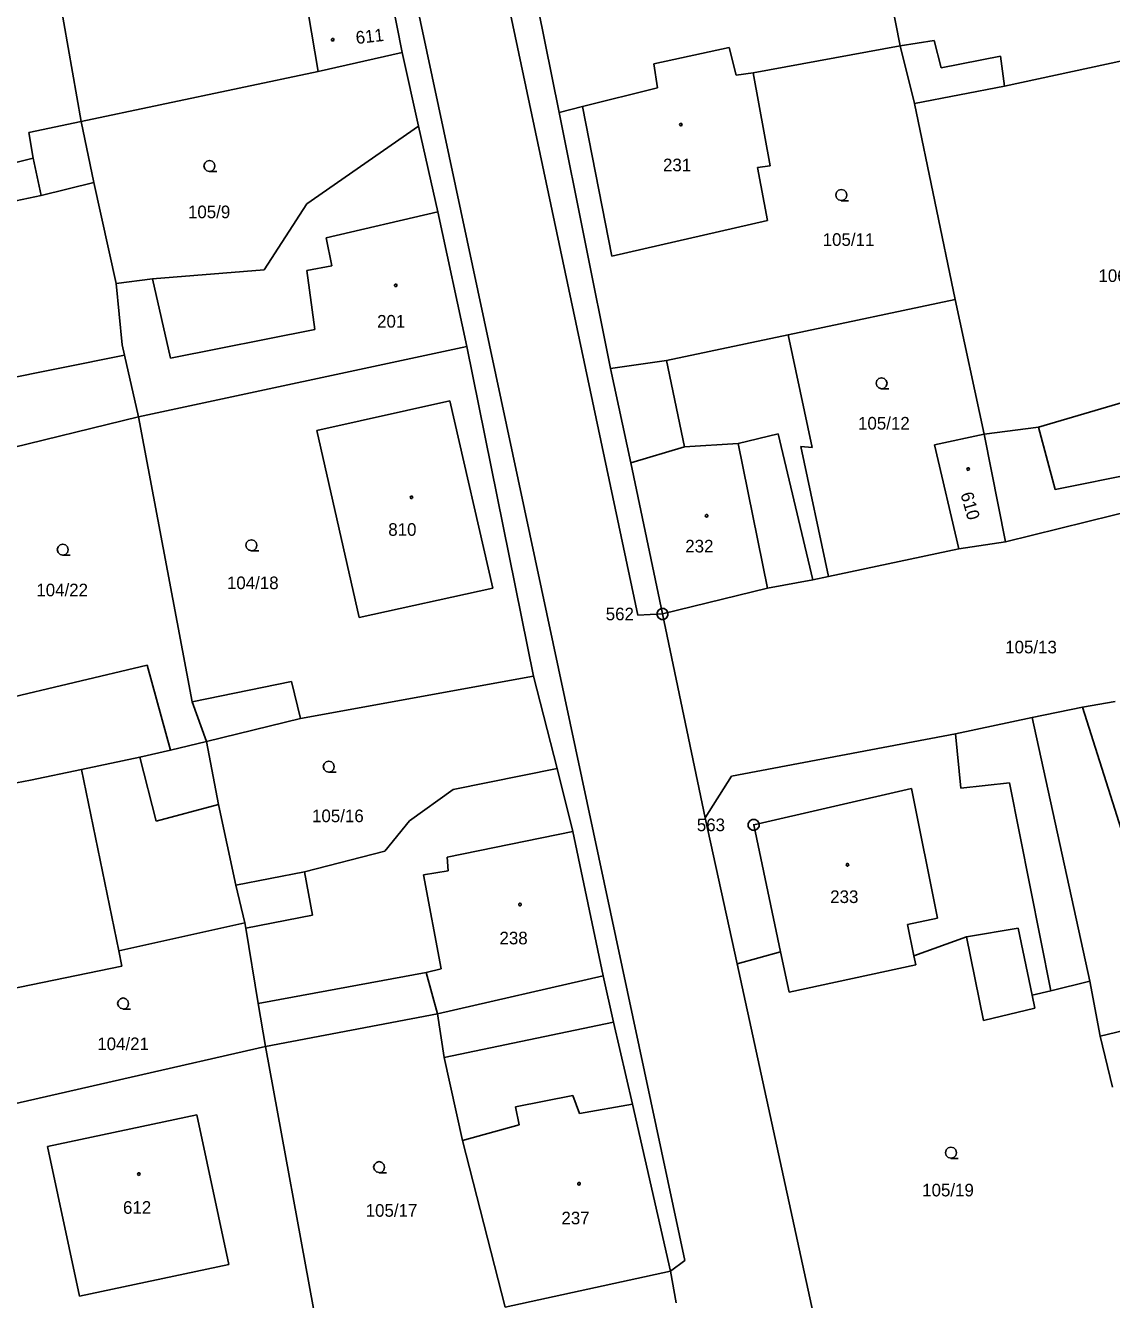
# Model space of a CAD drawing. Extents: x -757994 to -755874, y -1047691 to -1046119.
# Drawn here: x -756709.6 to -756636.5, y -1047105.4 to -1047019.6 of the extents above; entities that cross this region are included whole.
import ezdxf

# ---------------------------------------------------------------- set-up
doc = ezdxf.new("R2010")
doc.units = 0
doc.layers.add('katastrální mapa', color=7, linetype='Continuous')

msp = doc.modelspace()

# ---------------------------------------------------------------- linework, layer by layer
at = {"layer": 'katastrální mapa'}
for p, q in [((-756701.95, -1046901.14), (-756668.39, -1047059.3)), ((-756707.71, -1046903.74), (-756665.23, -1047102.74)), ((-756652.26, -1047013.32), (-756650.75, -1047021)), ((-756705.85, -1047026.09), (-756707.32, -1047017.76)), ((-756685, -1047017.62), (-756684.26, -1047021.44)), ((-756675.13, -1047018.38), (-756673.7, -1047025.49)), ((-756689.9, -1047022.72), (-756690.59, -1047018.75)), ((-756626.1, -1047019.92), (-756643.72, -1047023.72)), ((-756667.31, -1047022.22), (-756662.24, -1047021.12)), ((-756662.24, -1047021.12), (-756661.77, -1047022.98)), ((-756650.75, -1047021), (-756660.64, -1047022.81)), ((-756650.75, -1047021), (-756648.45, -1047020.63)), ((-756650.75, -1047021), (-756649.78, -1047024.89)), ((-756648.45, -1047020.63), (-756647.98, -1047022.47)), ((-756689.9, -1047022.72), (-756684.26, -1047021.44)), ((-756684.26, -1047021.44), (-756683.15, -1047026.41)), ((-756647.98, -1047022.47), (-756644, -1047021.7)), ((-756644, -1047021.7), (-756643.72, -1047023.72)), ((-756705.85, -1047026.09), (-756689.9, -1047022.72)), ((-756667.08, -1047023.83), (-756667.31, -1047022.22)), ((-756661.77, -1047022.98), (-756660.64, -1047022.81)), ((-756660.64, -1047022.81), (-756659.49, -1047029.08)), ((-756643.72, -1047023.72), (-756649.78, -1047024.89)), ((-756672.11, -1047025.09), (-756667.08, -1047023.83)), ((-756672.11, -1047025.09), (-756673.7, -1047025.49)), ((-756673.7, -1047025.49), (-756670.24, -1047042.72)), ((-756670.15, -1047035.16), (-756672.11, -1047025.09)), ((-756649.78, -1047024.89), (-756647.05, -1047038.07)), ((-756709.39, -1047026.83), (-756705.85, -1047026.09)), ((-756705, -1047030.19), (-756705.85, -1047026.09)), ((-756709.08, -1047028.56), (-756709.39, -1047026.83)), ((-756690.67, -1047031.63), (-756683.15, -1047026.41)), ((-756683.15, -1047026.41), (-756681.86, -1047032.17)), ((-756716.05, -1047030.25), (-756709.08, -1047028.56)), ((-756709.08, -1047028.56), (-756708.55, -1047031.06)), ((-756659.49, -1047029.08), (-756660.34, -1047029.18)), ((-756660.34, -1047029.18), (-756659.68, -1047032.76)), ((-756708.55, -1047031.06), (-756705, -1047030.19)), ((-756703.5, -1047037), (-756705, -1047030.19)), ((-756715.51, -1047032.52), (-756708.55, -1047031.06)), ((-756693.55, -1047036.07), (-756690.67, -1047031.63)), ((-756689.37, -1047033.91), (-756681.86, -1047032.17)), ((-756681.86, -1047032.17), (-756679.91, -1047041.22)), ((-756659.68, -1047032.76), (-756670.15, -1047035.16)), ((-756688.98, -1047035.8), (-756689.37, -1047033.91)), ((-756690.67, -1047036.11), (-756688.98, -1047035.8)), ((-756703.5, -1047037), (-756701.05, -1047036.67)), ((-756701.05, -1047036.67), (-756693.55, -1047036.07)), ((-756701.05, -1047036.67), (-756699.84, -1047042.02)), ((-756690.14, -1047040.09), (-756690.67, -1047036.11)), ((-756703.1, -1047041.13), (-756703.5, -1047037)), ((-756647.05, -1047038.07), (-756658.28, -1047040.45)), ((-756645.1, -1047047.13), (-756647.05, -1047038.07)), ((-756699.84, -1047042.02), (-756690.14, -1047040.09)), ((-756658.28, -1047040.45), (-756666.46, -1047042.18)), ((-756656.67, -1047048.03), (-756658.28, -1047040.45)), ((-756714.13, -1047044.07), (-756702.94, -1047041.82)), ((-756703.1, -1047041.13), (-756702.94, -1047041.82)), ((-756702.94, -1047041.82), (-756701.99, -1047045.97)), ((-756701.99, -1047045.97), (-756679.91, -1047041.22)), ((-756679.91, -1047041.22), (-756675.41, -1047063.42)), ((-756666.46, -1047042.18), (-756670.24, -1047042.72)), ((-756665.26, -1047047.98), (-756666.46, -1047042.18)), ((-756670.24, -1047042.72), (-756668.87, -1047049.07)), ((-756630.95, -1047043.56), (-756641.44, -1047046.67)), ((-756689.99, -1047046.88), (-756681.04, -1047044.88)), ((-756681.04, -1047044.88), (-756678.15, -1047057.5)), ((-756714.12, -1047048.91), (-756701.99, -1047045.97)), ((-756701.99, -1047045.97), (-756698.39, -1047065.15)), ((-756687.14, -1047059.47), (-756689.99, -1047046.88)), ((-756641.44, -1047046.67), (-756645.1, -1047047.13)), ((-756640.32, -1047050.86), (-756641.44, -1047046.67)), ((-756661.65, -1047047.76), (-756665.26, -1047047.98)), ((-756658.95, -1047047.11), (-756661.65, -1047047.76)), ((-756661.65, -1047047.76), (-756659.68, -1047057.5)), ((-756656.62, -1047056.93), (-756658.95, -1047047.11)), ((-756648.44, -1047047.84), (-756645.1, -1047047.13)), ((-756643.66, -1047054.37), (-756645.1, -1047047.13)), ((-756665.26, -1047047.98), (-756668.87, -1047049.07)), ((-756655.57, -1047056.71), (-756657.43, -1047047.95)), ((-756657.43, -1047047.95), (-756656.67, -1047048.03)), ((-756646.79, -1047054.84), (-756648.44, -1047047.84)), ((-756668.87, -1047049.07), (-756666.73, -1047059.23)), ((-756634.72, -1047049.74), (-756640.32, -1047050.86)), ((-756634.27, -1047052.06), (-756643.66, -1047054.37)), ((-756643.66, -1047054.37), (-756646.79, -1047054.84)), ((-756646.79, -1047054.84), (-756655.57, -1047056.71)), ((-756656.62, -1047056.93), (-756659.68, -1047057.5)), ((-756655.57, -1047056.71), (-756656.62, -1047056.93)), ((-756678.15, -1047057.5), (-756687.14, -1047059.47)), ((-756659.68, -1047057.5), (-756666.73, -1047059.23)), ((-756668.39, -1047059.3), (-756666.73, -1047059.23)), ((-756666.755, -1047059.23), (-756666.705, -1047059.23)), ((-756666.73, -1047059.23), (-756663.86, -1047072.95)), ((-756711.24, -1047065), (-756701.41, -1047062.67)), ((-756701.41, -1047062.67), (-756699.84, -1047068.39)), ((-756698.39, -1047065.15), (-756691.71, -1047063.77)), ((-756691.71, -1047063.77), (-756691.1, -1047066.27)), ((-756691.1, -1047066.27), (-756675.41, -1047063.42)), ((-756675.41, -1047063.42), (-756673.83, -1047069.63)), ((-756698.39, -1047065.15), (-756697.42, -1047067.82)), ((-756638.47, -1047065.5), (-756641.86, -1047066.19)), ((-756636.27, -1047065.11), (-756638.47, -1047065.5)), ((-756638.47, -1047065.5), (-756635.57, -1047074.64)), ((-756697.42, -1047067.82), (-756691.1, -1047066.27)), ((-756641.86, -1047066.19), (-756647.01, -1047067.29)), ((-756641.86, -1047066.19), (-756637.98, -1047083.94)), ((-756647.01, -1047067.29), (-756662.1, -1047070.15)), ((-756646.67, -1047070.94), (-756647.01, -1047067.29)), ((-756701.9, -1047068.86), (-756699.84, -1047068.39)), ((-756699.84, -1047068.39), (-756697.42, -1047067.82)), ((-756696.62, -1047072.05), (-756697.42, -1047067.82)), ((-756705.83, -1047069.69), (-756701.9, -1047068.86)), ((-756700.81, -1047073.17), (-756701.9, -1047068.86)), ((-756709.26, -1047070.42), (-756705.83, -1047069.69)), ((-756703.33, -1047081.9), (-756705.83, -1047069.69)), ((-756680.82, -1047071.04), (-756673.83, -1047069.63)), ((-756673.83, -1047069.63), (-756672.76, -1047073.87)), ((-756710.2, -1047070.6), (-756709.26, -1047070.42)), ((-756662.1, -1047070.15), (-756663.86, -1047072.95)), ((-756643.38, -1047070.59), (-756646.67, -1047070.94)), ((-756640.6, -1047084.58), (-756643.38, -1047070.59)), ((-756683.76, -1047073.16), (-756680.82, -1047071.04)), ((-756660.6, -1047073.42), (-756649.98, -1047070.98)), ((-756649.98, -1047070.98), (-756648.22, -1047079.7)), ((-756696.62, -1047072.05), (-756700.81, -1047073.17)), ((-756695.45, -1047077.48), (-756696.62, -1047072.05)), ((-756685.42, -1047075.2), (-756683.76, -1047073.16)), ((-756663.86, -1047072.95), (-756661.72, -1047082.77)), ((-756660.625, -1047073.42), (-756660.575, -1047073.42)), ((-756658.79, -1047081.96), (-756660.6, -1047073.42)), ((-756681.22, -1047075.59), (-756672.76, -1047073.87)), ((-756672.76, -1047073.87), (-756670.74, -1047083.58)), ((-756690.82, -1047076.57), (-756685.42, -1047075.2)), ((-756681.17, -1047076.51), (-756681.22, -1047075.59)), ((-756695.45, -1047077.48), (-756690.82, -1047076.57)), ((-756690.3, -1047079.49), (-756690.82, -1047076.57)), ((-756682.82, -1047076.79), (-756681.17, -1047076.51)), ((-756681.63, -1047083.1), (-756682.82, -1047076.79)), ((-756694.85, -1047080.01), (-756695.45, -1047077.48)), ((-756694.77, -1047080.37), (-756690.3, -1047079.49)), ((-756703.33, -1047081.9), (-756694.85, -1047080.01)), ((-756694.85, -1047080.01), (-756694.77, -1047080.37)), ((-756694.77, -1047080.37), (-756693.94, -1047085.44)), ((-756648.22, -1047079.7), (-756650.26, -1047080.13)), ((-756650.26, -1047080.13), (-756649.82, -1047082.24)), ((-756646.29, -1047080.96), (-756642.81, -1047080.37)), ((-756642.81, -1047080.37), (-756641.85, -1047084.89)), ((-756649.82, -1047082.24), (-756646.29, -1047080.96)), ((-756646.29, -1047080.96), (-756645.14, -1047086.58)), ((-756703.12, -1047082.93), (-756703.33, -1047081.9)), ((-756661.72, -1047082.77), (-756658.79, -1047081.96)), ((-756658.79, -1047081.96), (-756658.21, -1047084.68)), ((-756715.51, -1047085.47), (-756703.12, -1047082.93)), ((-756661.72, -1047082.77), (-756655.08, -1047113.24)), ((-756658.21, -1047084.68), (-756649.69, -1047082.85)), ((-756649.82, -1047082.24), (-756649.69, -1047082.85)), ((-756693.94, -1047085.44), (-756682.64, -1047083.35)), ((-756682.64, -1047083.35), (-756681.63, -1047083.1)), ((-756682.64, -1047083.35), (-756681.87, -1047086.13)), ((-756681.87, -1047086.13), (-756670.74, -1047083.58)), ((-756670.74, -1047083.58), (-756670.03, -1047086.69)), ((-756640.6, -1047084.58), (-756641.85, -1047084.89)), ((-756637.98, -1047083.94), (-756640.6, -1047084.58)), ((-756637.98, -1047083.94), (-756637.28, -1047087.64)), ((-756693.94, -1047085.44), (-756693.46, -1047088.33)), ((-756641.85, -1047084.89), (-756641.67, -1047085.76)), ((-756693.46, -1047088.33), (-756681.87, -1047086.13)), ((-756681.43, -1047089.07), (-756681.87, -1047086.13)), ((-756641.67, -1047085.76), (-756645.14, -1047086.58)), ((-756670.03, -1047086.69), (-756681.43, -1047089.07)), ((-756670.03, -1047086.69), (-756668.76, -1047092.21)), ((-756637.28, -1047087.64), (-756633.93, -1047086.84)), ((-756637.28, -1047087.64), (-756636.46, -1047091.06)), ((-756713.97, -1047093.01), (-756693.46, -1047088.33)), ((-756689.77, -1047108.45), (-756693.46, -1047088.33)), ((-756680.19, -1047094.66), (-756681.43, -1047089.07)), ((-756676.64, -1047092.4), (-756672.78, -1047091.63)), ((-756676.39, -1047093.61), (-756676.64, -1047092.4)), ((-756672.78, -1047091.63), (-756672.33, -1047092.84)), ((-756672.33, -1047092.84), (-756668.76, -1047092.21)), ((-756668.76, -1047092.21), (-756666.19, -1047103.45)), ((-756708.12, -1047095.07), (-756698.07, -1047092.93)), ((-756698.07, -1047092.93), (-756695.92, -1047103)), ((-756680.19, -1047094.66), (-756676.39, -1047093.61)), ((-756677.33, -1047105.87), (-756680.19, -1047094.66)), ((-756705.98, -1047105.14), (-756708.12, -1047095.07)), ((-756695.92, -1047103), (-756705.98, -1047105.14)), ((-756677.33, -1047105.87), (-756666.19, -1047103.45)), ((-756665.23, -1047102.74), (-756666.19, -1047103.45)), ((-756666.19, -1047103.45), (-756665.81, -1047105.58))]:
    msp.add_line(p, q, dxfattribs=at)
for points in [[(-756688.93, -1047020.505), (-756688.88, -1047020.515), (-756688.855, -1047020.56), (-756688.845, -1047020.59), (-756688.855, -1047020.635), (-756688.895, -1047020.67), (-756688.93, -1047020.675), (-756688.975, -1047020.66), (-756689.005, -1047020.63), (-756689.015, -1047020.59), (-756689.005, -1047020.545), (-756688.965, -1047020.51)], [(-756665.5, -1047026.215), (-756665.45, -1047026.225), (-756665.425, -1047026.27), (-756665.415, -1047026.3), (-756665.425, -1047026.345), (-756665.465, -1047026.38), (-756665.5, -1047026.385), (-756665.545, -1047026.37), (-756665.575, -1047026.34), (-756665.585, -1047026.3), (-756665.575, -1047026.255), (-756665.535, -1047026.22)], [(-756684.69, -1047037.035), (-756684.64, -1047037.045), (-756684.615, -1047037.09), (-756684.605, -1047037.12), (-756684.615, -1047037.165), (-756684.655, -1047037.2), (-756684.69, -1047037.205), (-756684.735, -1047037.19), (-756684.765, -1047037.16), (-756684.775, -1047037.12), (-756684.765, -1047037.075), (-756684.725, -1047037.04)], [(-756646.17, -1047049.395), (-756646.12, -1047049.405), (-756646.095, -1047049.45), (-756646.085, -1047049.48), (-756646.095, -1047049.525), (-756646.135, -1047049.56), (-756646.17, -1047049.565), (-756646.215, -1047049.55), (-756646.245, -1047049.52), (-756646.255, -1047049.48), (-756646.245, -1047049.435), (-756646.205, -1047049.4)], [(-756683.63, -1047051.295), (-756683.58, -1047051.305), (-756683.555, -1047051.35), (-756683.545, -1047051.38), (-756683.555, -1047051.425), (-756683.595, -1047051.46), (-756683.63, -1047051.465), (-756683.675, -1047051.45), (-756683.705, -1047051.42), (-756683.715, -1047051.38), (-756683.705, -1047051.335), (-756683.665, -1047051.3)], [(-756663.77, -1047052.535), (-756663.72, -1047052.545), (-756663.695, -1047052.59), (-756663.685, -1047052.62), (-756663.695, -1047052.665), (-756663.735, -1047052.7), (-756663.77, -1047052.705), (-756663.815, -1047052.69), (-756663.845, -1047052.66), (-756663.855, -1047052.62), (-756663.845, -1047052.575), (-756663.805, -1047052.54)], [(-756666.635, -1047058.87), (-756666.465, -1047058.965), (-756666.37, -1047059.135), (-756666.37, -1047059.33), (-756666.465, -1047059.5), (-756666.635, -1047059.595), (-756666.83, -1047059.595), (-756667, -1047059.5), (-756667.095, -1047059.33), (-756667.095, -1047059.135), (-756667, -1047058.965), (-756666.83, -1047058.87)], [(-756660.505, -1047073.06), (-756660.335, -1047073.155), (-756660.24, -1047073.325), (-756660.24, -1047073.52), (-756660.335, -1047073.69), (-756660.505, -1047073.785), (-756660.7, -1047073.785), (-756660.87, -1047073.69), (-756660.965, -1047073.52), (-756660.965, -1047073.325), (-756660.87, -1047073.155), (-756660.7, -1047073.06)], [(-756654.29, -1047076.025), (-756654.24, -1047076.035), (-756654.215, -1047076.08), (-756654.205, -1047076.11), (-756654.215, -1047076.155), (-756654.255, -1047076.19), (-756654.29, -1047076.195), (-756654.335, -1047076.18), (-756654.365, -1047076.15), (-756654.375, -1047076.11), (-756654.365, -1047076.065), (-756654.325, -1047076.03)], [(-756676.33, -1047078.695), (-756676.28, -1047078.705), (-756676.255, -1047078.75), (-756676.245, -1047078.78), (-756676.255, -1047078.825), (-756676.295, -1047078.86), (-756676.33, -1047078.865), (-756676.375, -1047078.85), (-756676.405, -1047078.82), (-756676.415, -1047078.78), (-756676.405, -1047078.735), (-756676.365, -1047078.7)], [(-756701.98, -1047096.835), (-756701.93, -1047096.845), (-756701.905, -1047096.89), (-756701.895, -1047096.92), (-756701.905, -1047096.965), (-756701.945, -1047097), (-756701.98, -1047097.005), (-756702.025, -1047096.99), (-756702.055, -1047096.96), (-756702.065, -1047096.92), (-756702.055, -1047096.875), (-756702.015, -1047096.84)], [(-756672.36, -1047097.485), (-756672.31, -1047097.495), (-756672.285, -1047097.54), (-756672.275, -1047097.57), (-756672.285, -1047097.615), (-756672.325, -1047097.65), (-756672.36, -1047097.655), (-756672.405, -1047097.64), (-756672.435, -1047097.61), (-756672.445, -1047097.57), (-756672.435, -1047097.525), (-756672.395, -1047097.49)]]:
    msp.add_lwpolyline(points, close=True, dxfattribs=at)
for points in [[(-756697.22, -1047029.45), (-756697.41, -1047029.4), (-756697.545, -1047029.265), (-756697.595, -1047029.08), (-756697.545, -1047028.895), (-756697.41, -1047028.76), (-756697.225, -1047028.71), (-756697.04, -1047028.76), (-756696.905, -1047028.895), (-756696.855, -1047029.085), (-756696.905, -1047029.275), (-756697.04, -1047029.41), (-756697.23, -1047029.46), (-756696.73, -1047029.46)], [(-756654.7, -1047031.41), (-756654.89, -1047031.36), (-756655.025, -1047031.225), (-756655.075, -1047031.04), (-756655.025, -1047030.855), (-756654.89, -1047030.72), (-756654.705, -1047030.67), (-756654.52, -1047030.72), (-756654.385, -1047030.855), (-756654.335, -1047031.045), (-756654.385, -1047031.235), (-756654.52, -1047031.37), (-756654.71, -1047031.42), (-756654.21, -1047031.42)], [(-756651.99, -1047044.07), (-756652.18, -1047044.02), (-756652.315, -1047043.885), (-756652.365, -1047043.7), (-756652.315, -1047043.515), (-756652.18, -1047043.38), (-756651.995, -1047043.33), (-756651.81, -1047043.38), (-756651.675, -1047043.515), (-756651.625, -1047043.705), (-756651.675, -1047043.895), (-756651.81, -1047044.03), (-756652, -1047044.08), (-756651.5, -1047044.08)], [(-756707.09, -1047055.27), (-756707.28, -1047055.22), (-756707.415, -1047055.085), (-756707.465, -1047054.9), (-756707.415, -1047054.715), (-756707.28, -1047054.58), (-756707.095, -1047054.53), (-756706.91, -1047054.58), (-756706.775, -1047054.715), (-756706.725, -1047054.905), (-756706.775, -1047055.095), (-756706.91, -1047055.23), (-756707.1, -1047055.28), (-756706.6, -1047055.28)], [(-756694.4, -1047054.97), (-756694.59, -1047054.92), (-756694.725, -1047054.785), (-756694.775, -1047054.6), (-756694.725, -1047054.415), (-756694.59, -1047054.28), (-756694.405, -1047054.23), (-756694.22, -1047054.28), (-756694.085, -1047054.415), (-756694.035, -1047054.605), (-756694.085, -1047054.795), (-756694.22, -1047054.93), (-756694.41, -1047054.98), (-756693.91, -1047054.98)], [(-756689.19, -1047069.87), (-756689.38, -1047069.82), (-756689.515, -1047069.685), (-756689.565, -1047069.5), (-756689.515, -1047069.315), (-756689.38, -1047069.18), (-756689.195, -1047069.13), (-756689.01, -1047069.18), (-756688.875, -1047069.315), (-756688.825, -1047069.505), (-756688.875, -1047069.695), (-756689.01, -1047069.83), (-756689.2, -1047069.88), (-756688.7, -1047069.88)], [(-756703.03, -1047085.81), (-756703.22, -1047085.76), (-756703.355, -1047085.625), (-756703.405, -1047085.44), (-756703.355, -1047085.255), (-756703.22, -1047085.12), (-756703.035, -1047085.07), (-756702.85, -1047085.12), (-756702.715, -1047085.255), (-756702.665, -1047085.445), (-756702.715, -1047085.635), (-756702.85, -1047085.77), (-756703.04, -1047085.82), (-756702.54, -1047085.82)], [(-756647.32, -1047095.85), (-756647.51, -1047095.8), (-756647.645, -1047095.665), (-756647.695, -1047095.48), (-756647.645, -1047095.295), (-756647.51, -1047095.16), (-756647.325, -1047095.11), (-756647.14, -1047095.16), (-756647.005, -1047095.295), (-756646.955, -1047095.485), (-756647.005, -1047095.675), (-756647.14, -1047095.81), (-756647.33, -1047095.86), (-756646.83, -1047095.86)], [(-756685.8, -1047096.82), (-756685.99, -1047096.77), (-756686.125, -1047096.635), (-756686.175, -1047096.45), (-756686.125, -1047096.265), (-756685.99, -1047096.13), (-756685.805, -1047096.08), (-756685.62, -1047096.13), (-756685.485, -1047096.265), (-756685.435, -1047096.455), (-756685.485, -1047096.645), (-756685.62, -1047096.78), (-756685.81, -1047096.83), (-756685.31, -1047096.83)]]:
    msp.add_lwpolyline(points, dxfattribs=at)

# ---------------------------------------------------------------- texts
for s, rotation, p in [('611', 6.53172, (-756687.335, -1047020.882)), ('610', 285.79135, (-756646.692, -1047051.154))]:
    msp.add_text(s, height=0.85, rotation=rotation, dxfattribs=at).set_placement(p)
for s, p in [('231', (-756666.703, -1047029.44)), ('105/9', (-756698.669, -1047032.6)), ('105/11', (-756655.956, -1047034.46)), ('106/5', (-756637.399, -1047036.89)), ('201', (-756685.943, -1047039.96)), ('105/12', (-756653.577, -1047046.82)), ('810', (-756685.191, -1047053.97)), ('232', (-756665.204, -1047055.09)), ('104/22', (-756708.874, -1047058.04)), ('104/18', (-756696.047, -1047057.56)), ('562', (-756670.557, -1047059.655)), ('105/13', (-756643.674, -1047061.88)), ('105/16', (-756690.32, -1047073.24)), ('563', (-756664.427, -1047073.845)), ('233', (-756655.451, -1047078.68)), ('238', (-756677.707, -1047081.46)), ('104/21', (-756704.773, -1047088.58)), ('105/19', (-756649.26, -1047098.42)), ('612', (-756703.04, -1047099.59)), ('105/17', (-756686.71, -1047099.79)), ('237', (-756673.537, -1047100.3))]:
    msp.add_text(s, height=0.85, dxfattribs=at).set_placement(p)

doc.saveas('drawing.dxf')
